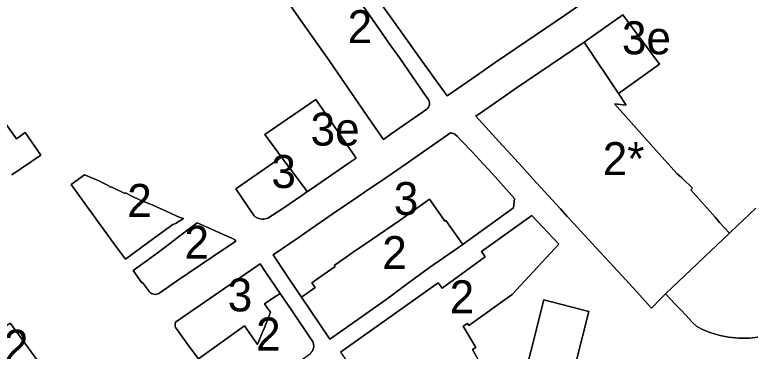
# Model space of a CAD drawing. Extents: x 598968 to 613553, y 4409678 to 4430833.
# Drawn here: x 608408.5 to 608676.3, y 4415663.9 to 4415786.4 of the extents above; entities that cross this region are included whole.
import ezdxf

# ---------------------------------------------------------------- set-up
doc = ezdxf.new("R2010")
doc.units = 0
for name, color, linetype in [('1', 7, 'Continuous'), ('SUBZONA 3e. EDIFICIS ENTRE MITGERES amb projecte especial', 7, 'Continuous'), ('ZONA 2. CARRERS DE CASES. Cases de trast', 7, 'Continuous'), ("ZONA 2_. CARRERS DE CASES. Afectades a ús d'aparcament", 7, 'Continuous'), ("ZONA 3. ILLES  D'EDIFICIS ENTRE MITGERES. EIXAMPLE.", 7, 'Continuous')]:
    doc.layers.add(name, color=color, linetype=linetype)

msp = doc.modelspace()

# ---------------------------------------------------------------- linework, layer by layer
at = {"layer": '1'}
for points in [[(608533.089, 4415792.5834), (608539.1589, 4415783.8037), (608545.2489, 4415775.1039), (608548.5188, 4415770.664), (608551.4688, 4415766.4241), (608554.3788, 4415762.1142), (608557.2488, 4415757.8343), (608559.0688, 4415755.3444), (608559.214, 4415754.8497), (608559.2736, 4415754.3375), (608559.2458, 4415753.8227), (608559.1314, 4415753.3199), (608558.9339, 4415752.8437), (608558.6587, 4415752.4077), (608558.3138, 4415752.0244), (608545.3976, 4415743.124), (608542.529, 4415741.0143), (608536.499, 4415749.804), (608522.7592, 4415769.7435), (608513.0793, 4415783.5132), (608501.5244, 4415800.1931)], [(608614.698, 4415790.5449), (608608.7881, 4415786.3949), (608598.1682, 4415779.2148), (608583.2184, 4415769.0046), (608576.3085, 4415764.1546), (608565.6587, 4415756.8845), (608562.4787, 4415761.3844), (608555.8788, 4415770.4441), (608548.3538, 4415781.0889), (608540.7589, 4415791.7836)], [(608678.6577, 4415669.1077), (608675.6878, 4415668.7176), (608671.791, 4415668.6967), (608668.0477, 4415669.0875), (608664.9878, 4415669.7274), (608661.5678, 4415670.6373), (608658.8678, 4415671.7873), (608656.4515, 4415672.9335), (608654.8552, 4415674.5289), (608652.4371, 4415677.15), (608650.7527, 4415678.918), (608648.6579, 4415681.117), (608645.1723, 4415684.7918), (608643.448, 4415683.0968), (608639.968, 4415679.6168), (608634.4581, 4415685.7666), (608629.3181, 4415691.3565), (608618.3682, 4415703.2761), (608611.6883, 4415710.5459), (608609.3983, 4415713.0459), (608606.8783, 4415715.8058), (608601.0984, 4415722.1256), (608596.9084, 4415726.7055), (608592.8384, 4415731.1553), (608588.9685, 4415735.3952), (608584.5185, 4415740.275), (608581.0285, 4415744.1449), (608576.1686, 4415749.5148), (608580.7417, 4415752.6543), (608590.4591, 4415759.4167), (608615.5591, 4415776.4868), (608629.616, 4415786.3506), (608642.9823, 4415768.4119), (608627.9997, 4415757.7255), (608630.7779, 4415753.5657), (608626.578, 4415753.9956), (608640.686, 4415738.2098), (608649.2723, 4415728.6025), (608651.0078, 4415727.0964), (608654.9077, 4415723.2565), (608654.3683, 4415722.7537), (608663.1296, 4415712.7516), (608664.8099, 4415710.8203), (608668.3876, 4415706.947), (608668.766, 4415707.2863), (608677.9789, 4415716.0018)], [(608404.5307, 4415747.7217), (608409.1106, 4415741.2618), (608412.2906, 4415743.6019), (608418.0005, 4415735.3621), (608407.4007, 4415728.102)], [(608526.8877, 4415663.6594), (608562.4889, 4415688.8653), (608563.8489, 4415686.9654), (608579.5587, 4415698.3255), (608578.2187, 4415700.2455), (608596.5583, 4415713.3348), (608606.3484, 4415702.8959), (608589.3786, 4415684.5559), (608573.6388, 4415673.2857), (608573.0889, 4415674.0457), (608571.5688, 4415673.0591), (608576.1088, 4415665.2859), (608574.9189, 4415664.5958), (608577.6388, 4415659.9159)], [(608475.2401, 4415661.2041), (608471.9401, 4415665.694), (608468.8601, 4415669.9039), (608467.3756, 4415671.9611), (608466.8902, 4415672.6338), (608466.8202, 4415673.0238), (608466.7886, 4415673.4447), (608466.7902, 4415673.9238), (608466.8746, 4415674.5267), (608497.693, 4415695.722), (608499.5659, 4415693.0136), (608501.6021, 4415690.0048), (608503.4297, 4415687.3043), (608505.0097, 4415684.9843), (608509.2496, 4415678.8045), (608516.4178, 4415668.1656), (608516.8496, 4415667.5248), (608517.1496, 4415666.6148), (608517.2096, 4415665.6548), (608517.1396, 4415665.1448), (608517.0296, 4415664.7148), (608516.6096, 4415663.8448)], [(608406.94, 4415674.051), (608419.7052, 4415656.5679), (608403.8649, 4415645.5793)]]:
    msp.add_lwpolyline(points, dxfattribs=at)
for points in [[(608532.6112, 4415734.2274), (608530.1251, 4415732.5285), (608514.7914, 4415722.0199), (608514.7503, 4415722.0758), (608513.1805, 4415720.9159), (608505.5574, 4415715.6916), (608500.5396, 4415712.3739), (608499.0442, 4415712.0622), (608498.3997, 4415712.0689), (608497.2197, 4415712.2938), (608496.3297, 4415712.6738), (608495.9197, 4415712.9238), (608495.5397, 4415713.2238), (608488.8197, 4415723.0736), (608505.5127, 4415734.6485), (608499.4676, 4415742.8763), (608517.9998, 4415755.5795)], [(608567.4387, 4415743.3447), (608567.9587, 4415743.2047), (608568.4487, 4415742.9947), (608569.3687, 4415742.2247), (608571.0687, 4415740.4348), (608574.8386, 4415736.4849), (608578.7486, 4415732.1951), (608582.1586, 4415728.4652), (608590.1985, 4415719.5654), (608589.8685, 4415716.1855), (608571.5111, 4415702.8859), (608571.4685, 4415702.8557), (608559.3101, 4415694.4024), (608551.1491, 4415688.4551), (608543.8392, 4415683.025), (608527.8994, 4415671.8049), (608523.0995, 4415668.3949), (608512.7296, 4415683.6845), (608508.1764, 4415690.4442), (608507.1899, 4415691.9066), (608502.4044, 4415699.0006), (608511.9039, 4415705.5313), (608515.9836, 4415708.3452), (608519.9333, 4415711.0863), (608524.2787, 4415714.051), (608532.5305, 4415719.681), (608537.2353, 4415722.8909), (608541.419, 4415725.7453), (608545.6861, 4415728.6566), (608550.4825, 4415731.9432), (608566.9187, 4415743.4047)], [(608466.9, 4415710.4333), (608465.9701, 4415710.0933), (608457.1402, 4415703.6932), (608448.7503, 4415697.4932), (608445.5003, 4415701.813), (608440.0504, 4415709.3329), (608434.5204, 4415716.9227), (608431.7205, 4415720.7627), (608428.9409, 4415724.5828), (608433.7804, 4415728.1925), (608438.7403, 4415726.0526), (608442.7103, 4415724.1527), (608443.3203, 4415723.5827), (608443.5303, 4415723.7527), (608448.4402, 4415721.4029), (608448.7102, 4415721.6229), (608451.2759, 4415720.2174), (608453.6402, 4415719.193), (608458.7101, 4415717.1631), (608463.72, 4415714.8631), (608468.2148, 4415712.8002), (608469.8011, 4415712.3009)], [(608479.9799, 4415708.3436), (608484.0177, 4415706.5714), (608487.3704, 4415705.0551), (608488.3998, 4415704.5938), (608488.8398, 4415704.0638), (608480.3184, 4415698.3623), (608467.3205, 4415689.433), (608461.2839, 4415685.2538), (608460.8965, 4415684.9976), (608460.4724, 4415684.8085), (608460.0229, 4415684.6917), (608459.5603, 4415684.6505), (608459.0973, 4415684.6858), (608458.6463, 4415684.7967), (608458.2198, 4415684.9803), (608457.8292, 4415685.2315), (608457.4852, 4415685.5435), (608454.9402, 4415688.9834), (608454.7319, 4415688.8381), (608451.5203, 4415693.3433), (608455.7302, 4415696.3833), (608460.2402, 4415699.6233), (608462.6501, 4415701.4834), (608466.2901, 4415704.2734), (608468, 4415705.5934), (608472.41, 4415708.9134), (608474.8299, 4415710.6435)], [(608598.1788, 4415603.687), (608593.3789, 4415584.9072), (608590.9589, 4415575.4472), (608590.7809, 4415574.4415), (608585.7797, 4415573.9678), (608582.4615, 4415573.5652), (608578.6159, 4415573.0441), (608574.3021, 4415572.4047), (608572.6429, 4415572.1915), (608576.9091, 4415589.2468), (608581.789, 4415608.0467), (608586.6788, 4415626.8865), (608591.3987, 4415645.3164), (608596.1486, 4415663.8662), (608600.8385, 4415682.6161), (608617.1983, 4415678.4764), (608612.5184, 4415659.7066), (608607.7285, 4415641.0067), (608602.9387, 4415622.2869)]]:
    msp.add_lwpolyline(points, close=True, dxfattribs=at)
at = {"layer": 'SUBZONA 3e. EDIFICIS ENTRE MITGERES amb projecte especial'}
for points in [[(608627.9997, 4415757.7255), (608642.9823, 4415768.4119), (608629.616, 4415786.3506), (608615.5591, 4415776.4868)], [(608514.7503, 4415722.0758), (608514.7914, 4415722.0199), (608530.1251, 4415732.5285), (608532.6112, 4415734.2274), (608517.9998, 4415755.5795), (608499.4676, 4415742.8763), (608505.5127, 4415734.6485)]]:
    msp.add_lwpolyline(points, close=True, dxfattribs=at)
at = {"layer": 'ZONA 2. CARRERS DE CASES. Cases de trast'}
for points in [[(608501.5244, 4415800.1931), (608513.0793, 4415783.5132), (608522.7592, 4415769.7435), (608536.499, 4415749.804), (608542.529, 4415741.0143), (608545.3976, 4415743.124), (608558.3138, 4415752.0244), (608558.6587, 4415752.4077), (608558.9339, 4415752.8437), (608559.1314, 4415753.3199), (608559.2458, 4415753.8227), (608559.2736, 4415754.3375), (608559.214, 4415754.8497), (608559.0688, 4415755.3444), (608557.2488, 4415757.8343), (608554.3788, 4415762.1142), (608551.4688, 4415766.4241), (608548.5188, 4415770.664), (608545.2489, 4415775.1039), (608539.1589, 4415783.8037), (608533.089, 4415792.5834)], [(608540.7589, 4415791.7836), (608548.3538, 4415781.0889), (608555.8788, 4415770.4441), (608562.4787, 4415761.3844), (608565.6587, 4415756.8845), (608576.3085, 4415764.1546), (608583.2184, 4415769.0046), (608598.1682, 4415779.2148), (608608.7881, 4415786.3949), (608614.698, 4415790.5449)], [(608407.4007, 4415728.102), (608418.0005, 4415735.3621), (608412.2906, 4415743.6019), (608409.1106, 4415741.2618), (608404.5307, 4415747.7217)]]:
    msp.add_lwpolyline(points, dxfattribs=at)
for points in [[(608442.7103, 4415724.1527), (608438.7403, 4415726.0526), (608433.7804, 4415728.1925), (608428.9409, 4415724.5828), (608431.7205, 4415720.7627), (608434.5204, 4415716.9227), (608440.0504, 4415709.3329), (608445.5003, 4415701.813), (608448.7503, 4415697.4932), (608457.1402, 4415703.6932), (608465.9701, 4415710.0933), (608466.9, 4415710.4333), (608469.8011, 4415712.3009), (608468.2148, 4415712.8002), (608463.72, 4415714.8631), (608458.7101, 4415717.1631), (608453.6402, 4415719.193), (608451.2759, 4415720.2174), (608448.7102, 4415721.6229), (608448.4402, 4415721.4029), (608443.5303, 4415723.7527), (608443.3203, 4415723.5827)], [(608571.4685, 4415702.8557), (608565.2176, 4415711.573), (608565.2088, 4415711.5851), (608564.8829, 4415711.3407), (608562.4991, 4415714.7751), (608559.3403, 4415719.3259), (608548.2214, 4415711.4517), (608533.7092, 4415701.5146), (608531.6793, 4415700.1646), (608528.9893, 4415698.1346), (608524.6594, 4415695.1646), (608524.9294, 4415694.8046), (608520.5996, 4415691.7443), (608516.5395, 4415688.8745), (608517.7195, 4415687.1145), (608512.7296, 4415683.6845), (608523.0995, 4415668.3949), (608527.8994, 4415671.8049), (608543.8392, 4415683.025), (608551.1491, 4415688.4551), (608559.3101, 4415694.4024)], [(608544.1993, 4415642.2056), (608549.2018, 4415644.867), (608577.6388, 4415659.9159), (608574.9189, 4415664.5958), (608576.1088, 4415665.2859), (608571.5688, 4415673.0591), (608573.0889, 4415674.0457), (608573.6388, 4415673.2857), (608589.3786, 4415684.5559), (608606.3484, 4415702.8959), (608596.5583, 4415713.3348), (608578.2187, 4415700.2455), (608579.5587, 4415698.3255), (608563.8489, 4415686.9654), (608562.4889, 4415688.8653), (608526.8877, 4415663.6594), (608538.8058, 4415646.6475), (608541.1893, 4415648.3254), (608544.0449, 4415642.5196)], [(608467.3205, 4415689.433), (608480.3184, 4415698.3623), (608488.8398, 4415704.0638), (608488.3998, 4415704.5938), (608487.3704, 4415705.0551), (608484.0177, 4415706.5714), (608479.9799, 4415708.3436), (608474.8299, 4415710.6435), (608472.41, 4415708.9134), (608468, 4415705.5934), (608466.2901, 4415704.2734), (608462.6501, 4415701.4834), (608460.2402, 4415699.6233), (608455.7302, 4415696.3833), (608451.5203, 4415693.3433), (608454.7319, 4415688.8381), (608454.9402, 4415688.9834), (608457.4852, 4415685.5435), (608457.8292, 4415685.2315), (608458.2198, 4415684.9803), (608458.6463, 4415684.7967), (608459.0973, 4415684.6858), (608459.5603, 4415684.6505), (608460.0229, 4415684.6917), (608460.4724, 4415684.8085), (608460.8965, 4415684.9976), (608461.2839, 4415685.2538)], [(608475.2401, 4415661.2041), (608488.13, 4415643.4645), (608500.9998, 4415652.6847), (608506.3597, 4415656.4647), (608514.2592, 4415661.9502), (608515.9796, 4415663.1148), (608516.6096, 4415663.8448), (608517.0296, 4415664.7148), (608517.1396, 4415665.1448), (608517.2096, 4415665.6548), (608517.1496, 4415666.6148), (608516.8496, 4415667.5248), (608516.4178, 4415668.1656), (608509.2496, 4415678.8045), (608505.0097, 4415684.9843), (608502.3697, 4415683.2343), (608499.2498, 4415681.1843), (608500.3897, 4415679.6243), (608501.4897, 4415678.1243), (608499.1201, 4415672.2043), (608498.4798, 4415670.6044), (608496.7998, 4415666.4044), (608492.0099, 4415673.2242), (608483.92, 4415667.4042)], [(608403.6097, 4415645.5), (608403.8649, 4415645.5793), (608419.7052, 4415656.5679), (608406.94, 4415674.051), (608406.7109, 4415674.1127), (608389.3811, 4415661.0925), (608395.714, 4415652.6079), (608395.7448, 4415652.6311), (608397.7489, 4415654.1331), (608397.7601, 4415654.1175), (608399.1543, 4415652.1675)]]:
    msp.add_lwpolyline(points, close=True, dxfattribs=at)
at = {"layer": "ZONA 2_. CARRERS DE CASES. Afectades a ús d'aparcament"}
msp.add_lwpolyline([(608627.9997, 4415757.7255), (608615.5591, 4415776.4868), (608590.4591, 4415759.4167), (608580.7417, 4415752.6543), (608576.1686, 4415749.5148), (608581.0285, 4415744.1449), (608584.5185, 4415740.275), (608588.9685, 4415735.3952), (608592.8384, 4415731.1553), (608596.9084, 4415726.7055), (608601.0984, 4415722.1256), (608606.8783, 4415715.8058), (608609.3983, 4415713.0459), (608611.6883, 4415710.5459), (608618.3682, 4415703.2761), (608629.3181, 4415691.3565), (608634.4581, 4415685.7666), (608639.968, 4415679.6168), (608643.448, 4415683.0968), (608645.1723, 4415684.7918), (608668.3876, 4415706.947), (608664.8099, 4415710.8203), (608663.1296, 4415712.7516), (608654.3683, 4415722.7537), (608654.9077, 4415723.2565), (608651.0078, 4415727.0964), (608649.2723, 4415728.6025), (608640.686, 4415738.2098), (608626.578, 4415753.9956), (608630.7779, 4415753.5657)], close=True, dxfattribs=at)
at = {"layer": "ZONA 3. ILLES  D'EDIFICIS ENTRE MITGERES. EIXAMPLE."}
for points in [[(608571.4685, 4415702.8557), (608571.5111, 4415702.8859), (608589.8685, 4415716.1855), (608590.1985, 4415719.5654), (608582.1586, 4415728.4652), (608578.7486, 4415732.1951), (608574.8386, 4415736.4849), (608571.0687, 4415740.4348), (608569.3687, 4415742.2247), (608568.4487, 4415742.9947), (608567.9587, 4415743.2047), (608567.4387, 4415743.3447), (608566.9187, 4415743.4047), (608550.4825, 4415731.9432), (608545.6861, 4415728.6566), (608541.419, 4415725.7453), (608537.2353, 4415722.8909), (608532.5305, 4415719.681), (608524.2787, 4415714.051), (608519.9333, 4415711.0863), (608515.9836, 4415708.3452), (608511.9039, 4415705.5313), (608502.4044, 4415699.0006), (608507.1899, 4415691.9066), (608508.1764, 4415690.4442), (608512.7296, 4415683.6845), (608517.7195, 4415687.1145), (608516.5395, 4415688.8745), (608520.5996, 4415691.7443), (608524.9294, 4415694.8046), (608524.6594, 4415695.1646), (608528.9893, 4415698.1346), (608531.6793, 4415700.1646), (608533.7092, 4415701.5146), (608548.2214, 4415711.4517), (608559.3403, 4415719.3259), (608562.4991, 4415714.7751), (608564.8829, 4415711.3407), (608565.2088, 4415711.5851), (608565.2176, 4415711.573)], [(608514.7503, 4415722.0758), (608505.5127, 4415734.6485), (608488.8197, 4415723.0736), (608495.5397, 4415713.2238), (608495.9197, 4415712.9238), (608496.3297, 4415712.6738), (608497.2197, 4415712.2938), (608498.3997, 4415712.0689), (608499.0442, 4415712.0622), (608500.5396, 4415712.3739), (608505.5574, 4415715.6916), (608513.1805, 4415720.9159)], [(608505.0097, 4415684.9843), (608503.4297, 4415687.3043), (608501.6021, 4415690.0048), (608499.5659, 4415693.0136), (608497.693, 4415695.722), (608466.8746, 4415674.5267), (608466.7902, 4415673.9238), (608466.7886, 4415673.4447), (608466.8202, 4415673.0238), (608466.8902, 4415672.6338), (608467.3756, 4415671.9611), (608468.8601, 4415669.9039), (608471.9401, 4415665.694), (608475.2401, 4415661.2041), (608483.92, 4415667.4042), (608492.0099, 4415673.2242), (608496.7998, 4415666.4044), (608498.4798, 4415670.6044), (608499.1201, 4415672.2043), (608501.4897, 4415678.1243), (608500.3897, 4415679.6243), (608499.2498, 4415681.1843), (608502.3697, 4415683.2343)], [(608574.3021, 4415572.4047), (608578.6159, 4415573.0441), (608582.4615, 4415573.5652), (608585.7797, 4415573.9678), (608590.7809, 4415574.4415), (608590.9589, 4415575.4472), (608593.3789, 4415584.9072), (608598.1788, 4415603.687), (608602.9387, 4415622.2869), (608607.7285, 4415641.0067), (608612.5184, 4415659.7066), (608617.1983, 4415678.4764), (608600.8385, 4415682.6161), (608596.1486, 4415663.8662), (608591.3987, 4415645.3164), (608586.6788, 4415626.8865), (608581.789, 4415608.0467), (608576.9091, 4415589.2468), (608572.6429, 4415572.1915)]]:
    msp.add_lwpolyline(points, close=True, dxfattribs=at)
msp.add_lwpolyline([(608677.9789, 4415716.0018), (608668.766, 4415707.2863), (608668.3876, 4415706.947), (608645.1723, 4415684.7918), (608648.6579, 4415681.117), (608650.7527, 4415678.918), (608652.4371, 4415677.15), (608654.8552, 4415674.5289), (608656.4515, 4415672.9335), (608658.8678, 4415671.7873), (608661.5678, 4415670.6373), (608664.9878, 4415669.7274), (608668.0477, 4415669.0875), (608671.791, 4415668.6967), (608675.6878, 4415668.7176), (608678.6577, 4415669.1077)], dxfattribs=at)

# ---------------------------------------------------------------- texts
at = {"layer": 'SUBZONA 3e. EDIFICIS ENTRE MITGERES amb projecte especial'}
for p in [(608629.2707, 4415772.0381), (608516.0394, 4415738.7997)]:
    msp.add_text('3e', height=12, dxfattribs=at).set_placement(p)
at = {"layer": 'ZONA 2. CARRERS DE CASES. Cases de trast'}
for p in [(608529.5224, 4415776.0887), (608449.371, 4415712.8429), (608470.1801, 4415697.647), (608542.0991, 4415693.8604), (608566.618, 4415677.7702), (608496.2248, 4415664.2244), (608404.5431, 4415659.8064)]:
    msp.add_text('2', height=12, dxfattribs=at).set_placement(p)
at = {"layer": "ZONA 2_. CARRERS DE CASES. Afectades a ús d'aparcament"}
msp.add_text('2*', height=12, dxfattribs=at).set_placement((608622.2781, 4415728.0518))
at = {"layer": "ZONA 3. ILLES  D'EDIFICIS ENTRE MITGERES. EIXAMPLE."}
for p in [(608501.785, 4415723.3553), (608546.3015, 4415713.5446), (608485.8991, 4415678.463)]:
    msp.add_text('3', height=12, dxfattribs=at).set_placement(p)

doc.saveas('drawing.dxf')
